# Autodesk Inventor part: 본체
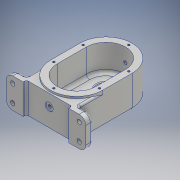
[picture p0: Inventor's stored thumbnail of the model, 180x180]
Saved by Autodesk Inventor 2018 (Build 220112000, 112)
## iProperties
Created: 2021-05
Part Number: 본체
Material: 알루미늄 6061
Document SubType Name: Modeling
Designer: Admin
Density: 2.7 g/cm^3
Appearance: 알루미늄 - 평지
Mass: 756.75 g
Surface Area: 581.943 cm^2
Volume: 280.278 cm^3
Author: Admin
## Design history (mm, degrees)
sketch "스케치1"
  geometry: L1 (0, -22.5)-(0, 22.5); L2 (40, -22.5)-(40, 22.5); L3 (-40, 22.5)-(-40, -22.5); L4 (-85.4, 0)-(85.4, 0) reference; L5 (0, -95.9)-(0, 88.9) reference; A1 r 40 centre (0, -22.5) between (-40, -22.5) and (40, -22.5); A2 r 40 centre (0, 22.5) between (40, 22.5) and (-40, 22.5); 1 further point
  constraints: 8 end point, 4 point on circle, 4 tangent, 2 centre point, 1 collinear, 1 midpoint, 1 parallel
  dimensions: "d0" = 45 distance of L1.start L1.end; "d1" = 80 distance between parallel lines of L3 L2
extrude "돌출1" new body sketch "스케치1" stored distance "d2" = 49; taper "d3" = 0 deg
node "작업 평면2"
sketch "스케치10"
  geometry: L1 (-85.4, 0)-(85.4, 0) reference; L2 (40, 22.5)-(40, -22.5) reference; L3 (-40, -22.5)-(-40, 22.5) reference; L4 (0, -95.9)-(0, 88.9) reference; L5 (-40, -22.5)-(-40, -59.5); L6 (-40, -59.5)-(-61, -59.5); L7 (-61, -59.5)-(-61, -69.5); L8 (-61, -69.5)-(0, -69.5); L9 (40, -22.5)-(40, -59.5); L10 (40, -59.5)-(61, -59.5); L11 (61, -59.5)-(61, -69.5); L12 (61, -69.5)-(0, -69.5); L13 (-40, -22.5)-(40, -22.5); A1 r 40 centre (0, -22.5) between (-40, -22.5) and (40, -22.5) reference; A2 r 40 centre (0, 22.5) between (40, 22.5) and (-40, 22.5) reference; 1 further point
  constraints: 18 end point, 4 symmetric about line, 3 perpendicular, 1 horizontal, 1 horizontal alignment, 1 point on line, 1 vertical
  dimensions: "d47" = 10 distance of L6.end L7.end; "d48" = 47 distance from line of A1.centre L8; "d49" = 61 distance of L7.end L8.end; "d50" = 40 distance between parallel lines of L4 L5
extrude "돌출8" join sketch "스케치10" distance "d51" = 46; taper "d52" = 0 deg
sketch "스케치2"
  geometry: L1 (40, -22.5)-(40, 22.5) reference; L2 (-40, 22.5)-(-40, -22.5) reference; L3 (0, -22.5)-(0, 22.5); L4 (-30, -22.5)-(-30, 22.5); L5 (30, 22.5)-(30, -22.5); A1 r 40 centre (0, 22.5) between (40, 22.5) and (-40, 22.5) reference; A2 r 40 centre (0, -22.5) between (-40, -22.5) and (40, -22.5) reference; A3 r 30 centre (0, -22.5) between (-30, -22.5) and (30, -22.5); A4 r 30 centre (0, 22.5) between (30, 22.5) and (-30, 22.5); 2 further points
  constraints: 8 end point, 4 point on circle, 4 tangent, 2 centre point, 1 midpoint, 1 parallel, 1 vertical
  dimensions: "d4" = 30 radius of A4
extrude "돌출2" cut sketch "스케치2" distance "d5" = 41; taper "d6" = 0 deg
sketch "스케치3"
  geometry: L1 (-40, 22.5)-(-40, -59.5) reference; L2 (40, -59.5)-(40, 22.5) reference; L3 (0, -22.5)-(0, 22.5); L4 (-26, -22.5)-(-26, 22.5); L5 (26, 22.5)-(26, -22.5); L6 (-40, -59.5)-(-61, -59.5) reference; L7 (-61, -59.5)-(-61, -69.5) reference; L8 (-61, -69.5)-(61, -69.5) reference; L9 (61, -69.5)-(61, -59.5) reference; L10 (61, -59.5)-(40, -59.5) reference; A1 r 40 centre (0, 22.5) between (40, 22.5) and (-40, 22.5) reference; A2 r 26 centre (0, -22.5) between (-26, -22.5) and (26, -22.5); A3 r 26 centre (0, 22.5) between (26, 22.5) and (-26, 22.5); 2 further points
  constraints: 8 end point, 4 point on circle, 4 tangent, 2 centre point, 1 midpoint, 1 parallel, 1 vertical
  dimensions: "d7" = 52 distance between parallel lines of L5 L4
extrude "돌출3" join sketch "스케치3" distance "d8" = 11; taper "d9" = 0 deg
sketch "스케치4"
  geometry: L1 (-26, 22.5)-(-26, -22.5) reference; L2 (26, -22.5)-(26, 22.5) reference; L3 (-26, 22.5)-(-26, -22.5) reference; L4 (-26, -7.5)-(26, -7.5); L5 (-26, 22.5)-(-26, -7.5); L6 (26, 22.5)-(26, -22.5) reference; L7 (26, 22.5)-(26, -7.5); L8 (40, 22.5)-(40, -22.5) reference; A1 r 26 centre (0, -22.5) between (-26, -22.5) and (26, -22.5) reference; A2 r 26 centre (0, 22.5) between (26, 22.5) and (-26, 22.5) reference; 1 further point
  constraints: 6 end point, 2 point on line, 1 collinear, 1 parallel, 1 perpendicular
  dimensions: "d10" = 30 distance from line of L4 A2.centre
extrude "돌출4" cut sketch "스케치4" distance "d11" = 3; taper "d12" = 0 deg
sketch "스케치6"
  geometry: C1 r 11 at (0, 22.5); A1 r 26 centre (0, 22.5) between (26, 22.5) and (-26, 22.5) reference; 1 further point
  constraints: 1 centre point, 1 coincident
  dimensions: "d15" = 22 diameter of C1
extrude "돌출5" cut sketch "스케치6" extent not by distance; stored distance "d16" = 4; taper "d17" = 0 deg
sketch "스케치7"
  geometry: C1 r 11 at (0, 22.5) reference; C2 r 14 at (0, 22.5); 1 further point
  constraints: 1 centre point, 1 coincident
  dimensions: "d18" = 28 diameter of C2
extrude "돌출6" cut sketch "스케치7" distance "d19" = 4; taper "d20" = 0 deg
sketch "스케치8"
  geometry: L1 (-30, -22.5)-(-30, 22.5) reference; L2 (30, 22.5)-(30, -22.5) reference; C1 r 14 at (0, 22.5); C2 r 14 at (0, -22.5); A1 r 30 centre (0, -22.5) between (-30, -22.5) and (30, -22.5) reference; A2 r 30 centre (0, 22.5) between (30, 22.5) and (-30, 22.5) reference; 1 further point
  constraints: 2 centre point, 2 coincident
  dimensions: "d21" = 28 diameter of C2; "d22" = 28 diameter of C1 (= d21)
extrude "돌출7" cut sketch "스케치8" distance "d23" = 8; taper "d24" = 0 deg
sketch "스케치11"
  geometry: L1 (-85.4, 0)-(85.4, 0) reference; L2 (0, -95.9)-(0, 88.9) reference; L3 (-61, -69.5)-(61, -69.5) reference; L4 (-35, -64.5)-(35, -64.5); L5 (35, -64.5)-(35, -69.5); L6 (35, -69.5)-(-35, -69.5); L7 (-35, -69.5)-(-35, -64.5); 1 further point
  constraints: 8 end point, 2 parallel, 1 horizontal, 1 perpendicular, 1 point on line, 1 other
  dimensions: "d53" = 70 distance of L4.start L4.end; "d54" = 5 distance of L4.end L5.end
extrude "돌출9" cut sketch "스케치11" extent not by distance; stored distance "d55" = 48; taper "d56" = 0 deg
sketch "스케치12"
  geometry: C1 r 14 at (0, 0) reference; C2 r 10 at (0, 0); 1 further point
  constraints: 1 centre point, 1 coincident
  dimensions: "d57" = 20 diameter of C2
extrude "돌출10" cut sketch "스케치12" distance "d58" = 4; taper "d59" = 0 deg
sketch "스케치14"
  geometry: L1 (-30, -22.5)-(-30, 22.5) reference; L2 (30, 22.5)-(30, -22.5) reference; L3 (40, -22.5)-(40, 22.5) reference; L4 (-40, 22.5)-(-40, -22.5) reference; L5 (0, -22.5)-(0, 22.5); L6 (35, -22.5)-(35, 22.5); L7 (-35, 22.5)-(-35, -22.5); L8 (-85.4, 0)-(85.4, 0) reference; A1 r 30 centre (0, -22.5) between (-30, -22.5) and (30, -22.5) reference; A2 r 30 centre (0, 22.5) between (30, 22.5) and (-30, 22.5) reference; A3 r 40 centre (0, 22.5) between (40, 22.5) and (-40, 22.5) reference; A4 r 40 centre (0, -22.5) between (-40, -22.5) and (40, -22.5) reference; A5 r 35 centre (0, -22.5) between (-35, -22.5) and (35, -22.5); A6 r 35 centre (0, 22.5) between (35, 22.5) and (-35, 22.5); 7 further points
  constraints: 8 end point, 5 point on circle, 4 tangent, 3 symmetric about line, 2 centre point, 2 coincident, 1 midpoint, 1 parallel, 1 vertical
  dimensions: "d60" = 35 radius of A6
hole "구멍1" sketch "스케치14" at (0, 57.5), (-35, 22.5), (35, 22.5), (0, -57.5), (-35, -22.5), (35, -22.5) diameter "d61" = 3.242; stored, may be unused: countersink angle "d65" = 90 deg, drill point angle "d67" = 118 deg; dims "d62" = 8, "d63" = 4, "d64" = 2, "d66" = 10
sketch "스케치15" dims "d68" = 40
  geometry: L1 (0, -95.9)-(0, 88.9) reference; C1 r 14 at (0, 22.5) reference; 5 further points
  constraints: 1 coincident, 1 point on line, 1 vertical alignment, 6 other
  dimensions: "d71" = 360 deg dimension on C1.centre point (0, 42.5) (derived)
hole "구멍2" sketch "스케치15" at (0, 42.5), (-17.321, 12.5), (17.321, 12.5) diameter "d73" = 3.242; stored, may be unused: countersink angle "d77" = 90 deg, drill point angle "d79" = 118 deg; dims "d74" = 8, "d75" = 4, "d76" = 2, "d78" = 10
node "작업 평면5"
  node "작업 평면4"
sketch "스케치16"
  geometry: L1 (40, 24.5)-(-40, 24.5) reference; L2 (0, -47.5)-(0, 36.5) reference; C1 r 6 at (0, 3.5)
  constraints: 1 centre point, 1 point on line
  dimensions: "d82" = 12 diameter of C1; "d121" = 21 distance from line of L1 C1.centre
extrude "돌출11" join sketch "스케치16" stored distance "d83" = 4; taper "d84" = 0 deg
sketch "스케치17"
  geometry: L1 (75, 3)-(-5, 3) reference; L2 (35, -69)-(35, 15) reference; 2 further points
  constraints: 1 point on line
  dimensions: "d85" = 21 distance from line of point (35, -18) L1
hole "구멍3" sketch "스케치17" at (35, -18) diameter "d86" = 4.917; stored, may be unused: countersink angle "d90" = 90 deg, drill point angle "d92" = 118 deg; dims "d87" = 12, "d88" = 12, "d89" = 1, "d91" = 17.1
sketch "스케치18"
  geometry: C1 r 6 at (0, 0) reference; 2 further points
  constraints: 1 coincident
hole "구멍4" sketch "스케치18" at (0, 0) diameter "d93" = 4.917; stored, may be unused: countersink angle "d97" = 90 deg, drill point angle "d99" = 118 deg; dims "d94" = 17, "d95" = 12, "d96" = 1, "d98" = 18
chamfer "모따기1" distance "d100" = 1; stored, may be unused: second distance "d101" = 2, angle "d102" = 45 deg
fillet "모깎기1" dims "d103" = 10, "d111" = 5, "d112" = 3
sketch "스케치20"
  geometry: A1 r 10 centre (-91, 36) between (-91, 46) and (-101, 36) reference; A2 r 10 centre (-91, 10) between (-101, 10) and (-91, 0) reference; A3 r 10 centre (11, 10) between (11, 0) and (21, 10) reference; A4 r 10 centre (11, 36) between (21, 36) and (11, 46) reference; 5 further points
  constraints: 4 coincident
hole "구멍5" sketch "스케치20" at (-91, 36), (-91, 10), (11, 10), (11, 36) diameter "d104" = 6.6; stored, may be unused: countersink angle "d108" = 90 deg, drill point angle "d110" = 118 deg; dims "d105" = 12, "d106" = 11, "d107" = 2, "d109" = 17.1
sketch "스케치21"
  geometry: L1 (0, -96.5)-(0, 92.5) reference; L2 (6, -64.5)-(-6, -64.5) reference; L3 (35, -69.5)-(51, -69.5) reference; 2 further points
  constraints: 1 point on line, 1 other
  dimensions: "d120" = 12 distance from line of L3 point (0, -57.5)
feature "엠보싱1" sketch "스케치21" dims "d0" = 45, "d1" = 80, "d5" = 41, "d114" = 0.5, "d115" = 0
fillet "모깎기2" dims "d116" = 3
fillet "모깎기3" dims "d117" = 3
fillet "모깎기4" dims "d118" = 3, "d119" = 0.3
node "솔리드1"
node "투영된 루프1"
node "투영된 루프2"
node "투영된 루프3"
node "투영된 루프5"
node "투영된 루프6"
node "투영된 루프7"
other parameters: "d29" = -3, "d81" = 3
